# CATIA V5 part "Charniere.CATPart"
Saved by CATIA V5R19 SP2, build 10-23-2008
Part number: Charniere
Publications: "diam_pivot", "largeur_pivot", "diam_trou_de_passage", "entraxe", "ep_oreille"
Bounding box of the stored display mesh (mm): x -7.954 to 7.954, y -30 to 26, z -18.5 to 18.5
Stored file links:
  F:\Projet CAO\pièces et assemblages\mécanisme 577\577-SaintAime\577-SaintAime\Charniere.CATPart
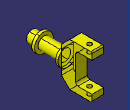
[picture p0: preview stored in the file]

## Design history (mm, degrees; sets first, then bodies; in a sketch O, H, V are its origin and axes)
Parameters
  ep_oreille = 6 mm
  entraxe = 25 mm
  diam_trou_de_passage = 4 mm
  Longueur_oreille = 14 mm {= diam_trou_de_passage +10 mm}
  Ray_pivot = 5 mm {= (diam_trou_de_passage/ 2) +3 mm}
  Ray_epaulement = 8 mm {= Ray_pivot + 3 mm}
  largeur_pivot = 18 mm
Body1 (main body)
  Sketch1 on yz-plane, origin (0, 0, 0), H (0, 1, 0), V (0, 0, 1)
    line L1 (-30, 5) -> (-22.5, 5)
    line L2 (-22.5, 5) -> (-22.5, 8)
    line L3 (-22.5, 8) -> (-20, 8)
    line L4 (-20, 8) -> (-20, 5)
    point P5 (-20, 5)
    line L5 (-20, 5) -> (-2, 5)
    line L6 (-2, 5) -> (-2, 8)
    point P7 (-2, 8)
    line L7 (-2, 8) -> (0, 8)
    point P8 (0, 8)
    line L8 (0, 8) -> (0, 0)
    line L9 (0, 0) -> (-30, 0)
    line L10 (-30, 0) -> (-30, 5)
    length L10 = 5 {= Ray_pivot}
    distance L3 H = 8 {= Ray_epaulement}
    distance L2 L4 = 2.5
    distance L6 L8 = 2
    distance L4 L6 = 18 {= largeur_pivot}
    distance L2 L10 = 7.5
    horizontal: L1 H, L3 H, L5 H, L7 H, L9 H
    vertical: L2 V, L4 V, L6 V, L8 V, L10 V
    coincidence: P5 L1, P7 L3, P8 V
  Shaft1: profile Sketch1, axis Sketch1.L9, angle 360
  Sketch2 on yz-plane, origin (0, 0, 0), H (0, 1, 0), V (0, 0, 1)
    projected line E1 (0, 8) -> (0, -8) from edge [face of Shaft1 from Sketch1.L7 | face of Shaft1 from Sketch1.L8]
    line L1 (0, 8) -> (0, 11.4289)
    line L2 (0, 11.4289) -> (7.0711, 18.5)
    line L3 (7.0711, 18.5) -> (26, 18.5)
    line L4 (26, 18.5) -> (26, 12.5)
    line L5 (26, 12.5) -> (14, 12.5)
    line L6 (12, 10.5) -> (12, -10.5)
    line L7 (14, -12.5) -> (26, -12.5)
    point P7 (26, -12.5)
    line L8 (26, -12.5) -> (26, -18.5)
    line L9 (26, -18.5) -> (7.0711, -18.5)
    line L10 (7.0711, -18.5) -> (0, -11.4289)
    point P10 (0, -11.4289)
    line L11 (0, -11.4289) -> (0, -8)
    arc A1 centre (14, 10.5) radius 2 from (12, 10.5) to (14, 12.5) cw
    arc A2 centre (14, -10.5) radius 2 from (14, -12.5) to (12, -10.5) cw
    distance L6 E1 = 12
    distance L5 L7 = 25 {= entraxe}
    distance L3 L5 = 6 {= ep_oreille}
    length L2 = 10
    distance L4 L6 = 14 {= Longueur_oreille}
    angle L10 E1 = 45
    radius A1 = 2
    radius A2 = 2
    vertical: L1 V, L4 V, L6 V, L8 V, L11 V
    horizontal: L3 H, L5 H, L7 H, L9 H
    coincidence: P7 L4, P10 V
    symmetry: L3 L9 H, L5 L7 H, L10 L2 H
    tangency: A1 L6, A1 L5, A2 L7, A2 L6
  Pad1: profile Sketch2, direction (1, 0, 0), length 5 {= (diam_trou_de_passage/ 2) +3 mm}, mirrored extent
  Sketch3 on face of Pad1 from Sketch2.L3, origin (0, 0, 18.5), H (1, 0, 0), V (0, 1, 0)
    circle A1 centre (0, 19) radius 2
    point P1 (0, 19)
    reference projected line E1 (5, 12) -> (-5, 12) from face of Pad1 from Sketch2.L6
    reference projected line E2 (-5, 26) -> (5, 26) from edge [face of Pad1 from Sketch2.L3 | face of Pad1 from Sketch2.L4]
    radius A1 = 2 {= diam_trou_de_passage /2}
    coincidence: P1 V
    equidistance: E1 E2 P1
  Pocket1: profile Sketch3, direction (0, 0, -1), through (limit type 3)
  Fillet1: radius 1, on edge [face of Pad1 from Sketch2.L3 | face of Pad1 from Sketch2.L4]; edge [face of Pad1 from Sketch2.L8 | face of Pad1 from Sketch2.L9]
